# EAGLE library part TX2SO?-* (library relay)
2 AMP. HIGH CAPACITY RELAY NAiS WITH HIGH SURGE VOLTAGE & HIGH BREAKDOWN VOLTAGE Source: http://www.mew-europe.com/.. en_ds_61022_0001.pdf
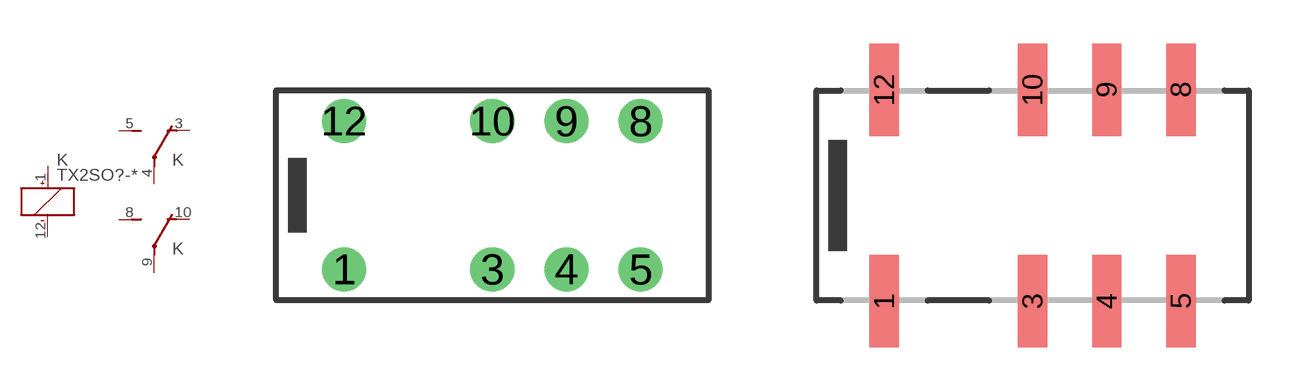
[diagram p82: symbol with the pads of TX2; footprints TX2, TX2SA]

Designator prefix K; gates _=K+- 1=U 2=U

## TX2SO-1.5V (OC_FARNELL: unknown; OC_NEWARK: unknown), TX2SO-3V (OC_FARNELL: unknown; OC_NEWARK: unknown), TX2SO-4.5V (OC_FARNELL: unknown; OC_NEWARK: unknown), TX2SO-5V (OC_FARNELL: unknown; OC_NEWARK: unknown), TX2SO-6V (OC_FARNELL: unknown; OC_NEWARK: unknown), TX2SO-9V (OC_FARNELL: unknown; OC_NEWARK: unknown), TX2SO-12V (OC_FARNELL: unknown; OC_NEWARK: unknown), TX2SO-24V (OC_FARNELL: unknown; OC_NEWARK: unknown)  [TX2]
1  _:+  pas
3  1:O  pas
4  1:P  pas
5  1:S  pas
8  2:S  pas
9  2:P  pas
10  2:O  pas
12  _:-  pas

## TX2SOSA-1.5V (OC_FARNELL: unknown; OC_NEWARK: unknown), TX2SOSA-3V (OC_FARNELL: unknown; OC_NEWARK: unknown), TX2SOSA-4.5V (OC_FARNELL: unknown; OC_NEWARK: unknown), TX2SOSA-5V (OC_FARNELL: unknown; OC_NEWARK: unknown), TX2SOSA-6V (OC_FARNELL: unknown; OC_NEWARK: unknown), TX2SOSA-9V (OC_FARNELL: unknown; OC_NEWARK: unknown), TX2SOSA-12V (OC_FARNELL: unknown; OC_NEWARK: unknown), TX2SOSA-24V (OC_FARNELL: unknown; OC_NEWARK: unknown), TX2SOSA-48V (OC_FARNELL: unknown; OC_NEWARK: unknown)  [TX2SA]
Pads as for TX2

## TX2SO-L-1.5V (OC_FARNELL: unknown; OC_NEWARK: unknown), TX2SO-L-3V (OC_FARNELL: unknown; OC_NEWARK: unknown), TX2SO-L-4.5V (OC_FARNELL: unknown; OC_NEWARK: unknown), TX2SO-L-5V (OC_FARNELL: unknown; OC_NEWARK: unknown), TX2SO-L-6V (OC_FARNELL: unknown; OC_NEWARK: unknown), TX2SO-L-9V (OC_FARNELL: unknown; OC_NEWARK: unknown), TX2SO-L-12V (OC_FARNELL: unknown; OC_NEWARK: unknown), TX2SO-L-24V (OC_FARNELL: unknown; OC_NEWARK: unknown)  [TX2]
1  _:-  pas
3  1:O  pas
4  1:P  pas
5  1:S  pas
8  2:S  pas
9  2:P  pas
10  2:O  pas
12  _:+  pas

## TX2SOSL-1.5V (OC_FARNELL: unknown; OC_NEWARK: unknown), TX2SOSL-3V (OC_FARNELL: unknown; OC_NEWARK: unknown), TX2SOSL-4.5V (OC_FARNELL: unknown; OC_NEWARK: unknown), TX2SOSL-5V (OC_FARNELL: unknown; OC_NEWARK: unknown), TX2SOSL-6V (OC_FARNELL: unknown; OC_NEWARK: unknown), TX2SOSL-9V (OC_FARNELL: unknown; OC_NEWARK: unknown), TX2SOSL-12V (OC_FARNELL: unknown; OC_NEWARK: unknown), TX2SOSL-24V (OC_FARNELL: unknown; OC_NEWARK: unknown), TX2SOSL-48V (OC_FARNELL: unknown; OC_NEWARK: unknown)  [TX2SL]
Pads as for TX2

## TX2SOSS-1.5V (OC_FARNELL: unknown; OC_NEWARK: unknown), TX2SOSS-3V (OC_FARNELL: unknown; OC_NEWARK: unknown), TX2SOSS-4.5V (OC_FARNELL: unknown; OC_NEWARK: unknown), TX2SOSS-5V (OC_FARNELL: unknown; OC_NEWARK: unknown), TX2SOSS-6V (OC_FARNELL: unknown; OC_NEWARK: unknown), TX2SOSS-9V (OC_FARNELL: unknown; OC_NEWARK: unknown), TX2SOSS-12V (OC_FARNELL: unknown; OC_NEWARK: unknown), TX2SOSS-24V (OC_FARNELL: unknown; OC_NEWARK: unknown), TX2SOSS-48V (OC_FARNELL: unknown; OC_NEWARK: unknown)  [TX2SS]
Pads as for TX2

## TX2SOSA-L-1.5V (OC_FARNELL: unknown; OC_NEWARK: unknown), TX2SOSA-L-3V (OC_FARNELL: unknown; OC_NEWARK: unknown), TX2SOSA-L-4.5V (OC_FARNELL: unknown; OC_NEWARK: unknown), TX2SOSA-L-5V (OC_FARNELL: unknown; OC_NEWARK: unknown), TX2SOSA-L-6V (OC_FARNELL: unknown; OC_NEWARK: unknown), TX2SOSA-L-9V (OC_FARNELL: unknown; OC_NEWARK: unknown), TX2SOSA-L-12V (OC_FARNELL: unknown; OC_NEWARK: unknown), TX2SOSA-L-24V (OC_FARNELL: unknown; OC_NEWARK: unknown)  [TX2SA]
Pads as for TX2

## TX2SOSL-L-1.5V (OC_FARNELL: unknown; OC_NEWARK: unknown), TX2SOSL-L-3V (OC_FARNELL: unknown; OC_NEWARK: unknown), TX2SOSL-L-4.5V (OC_FARNELL: unknown; OC_NEWARK: unknown), TX2SOSL-L-5V (OC_FARNELL: unknown; OC_NEWARK: unknown), TX2SOSL-L-6V (OC_FARNELL: unknown; OC_NEWARK: unknown), TX2SOSL-L-9V (OC_FARNELL: unknown; OC_NEWARK: unknown), TX2SOSL-L-12V (OC_FARNELL: unknown; OC_NEWARK: unknown), TX2SOSL-L-24V (OC_FARNELL: unknown; OC_NEWARK: unknown)  [TX2SL]
Pads as for TX2

## TX2SOSS-L-1.5V (OC_FARNELL: unknown; OC_NEWARK: unknown), TX2SOSS-L-3V (OC_FARNELL: unknown; OC_NEWARK: unknown), TX2SOSS-L-4.5V (OC_FARNELL: unknown; OC_NEWARK: unknown), TX2SOSS-L-5V (OC_FARNELL: unknown; OC_NEWARK: unknown), TX2SOSS-L-6V (OC_FARNELL: unknown; OC_NEWARK: unknown), TX2SOSS-L-9V (OC_FARNELL: unknown; OC_NEWARK: unknown), TX2SOSS-L-12V (OC_FARNELL: unknown; OC_NEWARK: unknown), TX2SOSS-L-24V (OC_FARNELL: unknown; OC_NEWARK: unknown)  [TX2SS]
Pads as for TX2

## Footprint TX2 (pad centres in mm)
2 AMP. HIGH CAPACITY RELAY NAiS WITH HIGH SURGE VOLTAGE & HIGH BREAKDOWN VOLTAGE Source: http://www.mew-europe.com/.. en_ds_61022_0001.pdf
drill 1 round: 1 -5.08,-2.54; 3 0,-2.54; 4 2.54,-2.54; 5 5.08,-2.54; 8 5.08,2.54; 9 2.54,2.54; 10 0,2.54; 12 -5.08,2.54

## Footprint TX2SA (pad centres in mm)
2 AMP. HIGH CAPACITY RELAY NAiS WITH HIGH SURGE VOLTAGE & HIGH BREAKDOWN VOLTAGE Source: http://www.mew-europe.com/.. en_ds_61022_0001.pdf
smd 1 x 3.16: 1 -5.08,-3.62; 3 0,-3.62; 4 2.54,-3.62; 5 5.08,-3.62; 8 5.08,3.62; 9 2.54,3.62; 10 0,3.62; 12 -5.08,3.62

## Footprint TX2SL (pad centres in mm)
2 AMP. HIGH CAPACITY RELAY NAiS WITH HIGH SURGE VOLTAGE & HIGH BREAKDOWN VOLTAGE Source: http://www.mew-europe.com/.. en_ds_61022_0001.pdf
smd 1 x 3.16: 1 -5.08,-3.62; 3 0,-3.62; 4 2.54,-3.62; 5 5.08,-3.62; 8 5.08,3.62; 9 2.54,3.62; 10 0,3.62; 12 -5.08,3.62

## Footprint TX2SS (pad centres in mm)
2 AMP. HIGH CAPACITY RELAY NAiS WITH HIGH SURGE VOLTAGE & HIGH BREAKDOWN VOLTAGE Source: http://www.mew-europe.com/.. en_ds_61022_0001.pdf
smd 1 x 2.16: 1 -5.08,-3.12; 3 0,-3.12; 4 2.54,-3.12; 5 5.08,-3.12; 8 5.08,3.12; 9 2.54,3.12; 10 0,3.12; 12 -5.08,3.12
